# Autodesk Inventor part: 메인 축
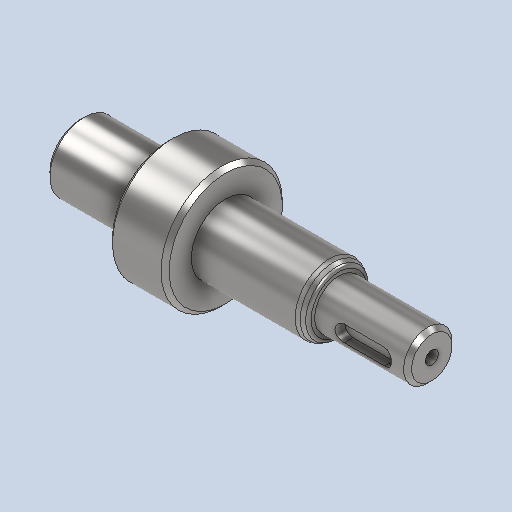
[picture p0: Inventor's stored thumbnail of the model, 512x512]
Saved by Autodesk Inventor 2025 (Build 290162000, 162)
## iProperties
Created: 2024-07
Part Number: 메인 축
Material: 강철, 연강
Document SubType Name: Modeling
Designer: 학생
Density: 7.86 g/cm^3
Appearance: 기본값
Author: jhkim
Revision Number: 1
Sending System: Autodesk Inventor 2025
Preprocessor: ST-DEVELOPER v20
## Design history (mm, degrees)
feature "솔리드1"
node "솔리드2"
